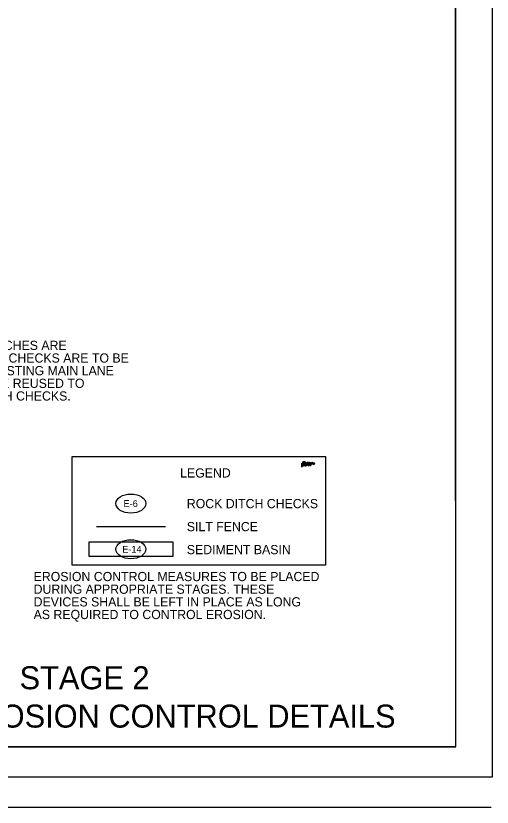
# Model space of a CAD drawing. Extents: x 9844 to 14104, y 9961 to 11067.
# Drawn here: x 11294 to 11605, y 9961 to 10477 of the extents above; entities that cross this region are included whole.
import ezdxf

# ---------------------------------------------------------------- set-up
doc = ezdxf.new("R2010")
doc.units = 0
for name, color, linetype in [('Legend', 7, 'Continuous'), ('R_Border', 7, 'Continuous'), ('R_No Plot', 7, 'Continuous'), ('R_NoPlot', 7, 'Continuous'), ('Stage 2 Ditch Checks', 7, 'Continuous'), ('TEXT', 7, 'Continuous')]:
    doc.layers.add(name, color=color, linetype=linetype)

msp = doc.modelspace()

# ---------------------------------------------------------------- linework, layer by layer
at = {"layer": 'Legend'}
for p, q in [((11480.29, 10183.63), (11481.49, 10184.33)), ((11480.29, 10183.1), (11481.69, 10183.92)), ((11480.29, 10182.58), (11481.9, 10183.5)), ((11481.57, 10185.41), (11482.5, 10185.41)), ((11482.52, 10185.39), (11482.62, 10184.8)), ((11483.84, 10184.29), (11483.84, 10184.3)), ((11483.84, 10183.49), (11483.84, 10183.49)), ((11483.85, 10185.3), (11483.85, 10185.3)), ((11483.85, 10184.49), (11483.85, 10184.49)), ((11483.85, 10183.51), (11483.85, 10183.51)), ((11483.86, 10183.46), (11484.04, 10183.46)), ((11483.87, 10184.51), (11483.87, 10184.51)), ((11483.87, 10184.47), (11484.05, 10184.47)), ((11483.87, 10184.25), (11483.87, 10183.53)), ((11483.88, 10185.26), (11483.88, 10184.54)), ((11484.03, 10183.97), (11484.03, 10184.19)), ((11484.03, 10183.53), (11484.03, 10183.85)), ((11484.04, 10184.92), (11484.04, 10185.21)), ((11484.05, 10184.54), (11484.05, 10184.77)), ((11484.05, 10183.5), (11484.05, 10183.51)), ((11484.06, 10184.8), (11484.31, 10184.87)), ((11484.06, 10184.51), (11484.06, 10184.51)), ((11484.06, 10184.21), (11484.45, 10184.21)), ((11484.34, 10183.95), (11484.06, 10183.95)), ((11484.06, 10183.87), (11484.34, 10183.87)), ((11484.06, 10183.49), (11484.06, 10183.49)), ((11484.07, 10185.24), (11484.15, 10185.24)), ((11484.2, 10184.96), (11484.08, 10184.9)), ((11484.08, 10184.49), (11484.08, 10184.49)), ((11484.37, 10183.84), (11484.37, 10183.83)), ((11484.49, 10184.18), (11484.49, 10184.16)), ((11484.61, 10184.49), (11484.61, 10184.49)), ((11484.62, 10183.47), (11484.83, 10183.47)), ((11484.63, 10184.47), (11484.84, 10184.47)), ((11484.78, 10184.05), (11484.63, 10184.05)), ((11484.63, 10184.01), (11484.63, 10184.01)), ((11484.64, 10185.02), (11484.64, 10185.01)), ((11484.64, 10183.99), (11484.64, 10183.53)), ((11484.79, 10185.06), (11484.65, 10185.06)), ((11484.66, 10184.99), (11484.66, 10184.54)), ((11484.8, 10183.54), (11484.8, 10184.03)), ((11484.82, 10184.54), (11484.82, 10185.04)), ((11484.83, 10183.51), (11484.83, 10183.51)), ((11484.84, 10184.51), (11484.84, 10184.52)), ((11485, 10183.46), (11485.21, 10183.46)), ((11485.16, 10184.05), (11485.01, 10184.05)), ((11485.01, 10184.01), (11485.01, 10184.01)), ((11485.02, 10183.99), (11485.02, 10183.53)), ((11485.18, 10183.53), (11485.18, 10183.86)), ((11485.21, 10183.51), (11485.21, 10183.51)), ((11485.38, 10184.9), (11485.45, 10184.98)), ((11485.53, 10184.47), (11485.73, 10184.47)), ((11485.53, 10184.01), (11485.53, 10184.01)), ((11485.68, 10185.32), (11485.54, 10185.32)), ((11485.54, 10185.28), (11485.54, 10185.28)), ((11485.54, 10183.99), (11485.54, 10183.53)), ((11485.55, 10185.26), (11485.55, 10184.53)), ((11485.71, 10184.86), (11485.71, 10185.3)), ((11485.71, 10184.69), (11485.78, 10184.75)), ((11485.71, 10184.53), (11485.71, 10184.67)), ((11485.71, 10183.54), (11485.71, 10183.86)), ((11485.73, 10183.51), (11485.73, 10183.51)), ((11485.9, 10184.97), (11485.75, 10184.84)), ((11485.82, 10184.74), (11485.94, 10184.53)), ((11485.89, 10185.04), (11485.9, 10185)), ((11486.12, 10185.07), (11485.91, 10185.07)), ((11485.91, 10183.51), (11485.91, 10183.51)), ((11485.93, 10184.47), (11486.19, 10184.47)), ((11485.93, 10183.86), (11485.93, 10183.54)), ((11485.95, 10184.9), (11486.1, 10185.03)), ((11486.15, 10184.52), (11485.95, 10184.87)), ((11486.09, 10183.54), (11486.09, 10183.87)), ((11486.12, 10185.03), (11486.13, 10185.03)), ((11486.12, 10183.51), (11486.12, 10183.51)), ((11486.14, 10185.04), (11486.14, 10185.05)), ((11486.32, 10184.9), (11486.32, 10184.9)), ((11486.32, 10183.87), (11486.32, 10183.53)), ((11486.33, 10184.82), (11486.68, 10184.82)), ((11486.53, 10184.87), (11486.34, 10184.87)), ((11486.48, 10183.54), (11486.48, 10183.87)), ((11486.51, 10183.51), (11486.5, 10183.51)), ((11486.68, 10184.62), (11486.68, 10184.62)), ((11486.78, 10184.47), (11487, 10184.47)), ((11486.79, 10185.02), (11486.79, 10185.01)), ((11486.95, 10185.06), (11486.8, 10185.06)), ((11486.81, 10184.99), (11486.81, 10184.54)), ((11486.97, 10184.54), (11486.97, 10184.87)), ((11487, 10184.51), (11486.99, 10184.52)), ((11487.25, 10184.47), (11487.46, 10184.47)), ((11487.26, 10185.02), (11487.26, 10185.01)), ((11487.42, 10185.06), (11487.27, 10185.06)), ((11487.28, 10184.99), (11487.28, 10184.54)), ((11487.44, 10184.54), (11487.44, 10185.03)), ((11487.46, 10184.51), (11487.46, 10184.52)), ((11487.57, 10184.47), (11487.78, 10184.47)), ((11487.58, 10185.02), (11487.58, 10185.01)), ((11487.73, 10185.06), (11487.59, 10185.06)), ((11487.6, 10184.99), (11487.6, 10184.54)), ((11487.76, 10184.54), (11487.76, 10184.87)), ((11487.78, 10184.51), (11487.78, 10184.52)), ((11487.96, 10184.47), (11488.17, 10184.47)), ((11487.98, 10184.87), (11487.98, 10184.54)), ((11488.14, 10184.54), (11488.14, 10184.87)), ((11488.17, 10184.51), (11488.17, 10184.52)), ((11488.84, 10185.06), (11488.61, 10185.06)), ((11488.67, 10184.94), (11488.67, 10184.65)), ((11488.69, 10184.46), (11488.69, 10184.46)), ((11488.81, 10184.63), (11488.81, 10184.98)), ((11488.82, 10185), (11488.86, 10185.02)), ((11346.58, 10143.59), (11391.58, 10143.59))]:
    msp.add_line(p, q, dxfattribs=at)
msp.add_lwpolyline([(11330.89, 10189.39), (11495.89, 10189.39), (11495.89, 10118.34), (11330.89, 10118.34)], close=True, dxfattribs=at)
for points in [[(11482.95, 10185.07), (11482.83, 10185.76), (11482.81, 10185.78), (11481.24, 10185.78), (11481.22, 10185.76), (11481.09, 10185.05), (11480.25, 10184.57), (11480.24, 10184.54), (11480.24, 10184.17), (11480.28, 10184.15)], [(11481.33, 10184.66), (11480.26, 10184.04), (11480.25, 10184.02), (11480.25, 10183.65), (11480.29, 10183.63)], [(11481.52, 10184.26), (11480.26, 10183.52), (11480.25, 10183.5), (11480.25, 10183.12), (11480.29, 10183.1)], [(11481.72, 10183.86), (11480.26, 10182.99), (11480.25, 10182.97), (11480.25, 10182.6), (11480.29, 10182.58)], [(11480.28, 10184.15), (11481.42, 10184.78), (11481.43, 10184.8), (11481.54, 10185.39)], [(11483.34, 10184.59), (11483.36, 10184.61), (11483.36, 10184.93), (11483.34, 10184.96)], [(11483.34, 10184.14), (11483.36, 10184.17), (11483.36, 10184.49), (11483.34, 10184.51)], [(11483.34, 10183.69), (11483.36, 10183.71), (11483.36, 10184.04), (11483.34, 10184.06)], [(11483.34, 10183.23), (11483.36, 10183.25), (11483.36, 10183.59), (11483.34, 10183.62)], [(11484.49, 10184.32), (11483.86, 10184.32), (11483.86, 10184.32)], [(11484.24, 10185.33), (11483.87, 10185.33), (11483.87, 10185.32)], [(11484.38, 10184.01), (11484.39, 10184.01), (11484.38, 10184.01), (11484.37, 10184), (11484.37, 10183.98)], [(11484.38, 10183.82), (11484.39, 10183.82), (11484.38, 10183.82)], [(11484.39, 10183.83), (11484.4, 10183.83), (11484.4, 10184), (11484.39, 10184)], [(11484.51, 10184.16), (11484.52, 10184.16), (11484.52, 10184.3)], [(11484.6, 10183.49), (11484.6, 10183.49), (11484.6, 10183.49)], [(11484.61, 10184.03), (11484.61, 10184.03), (11484.61, 10184.03)], [(11484.62, 10185.04), (11484.62, 10185.04), (11484.62, 10185.04)], [(11484.62, 10183.51), (11484.62, 10183.51), (11484.62, 10183.51)], [(11484.63, 10184.52), (11484.63, 10184.52), (11484.63, 10184.51)], [(11484.85, 10183.49), (11484.85, 10183.49), (11484.85, 10183.49)], [(11484.86, 10184.49), (11484.86, 10184.49), (11484.86, 10184.49)], [(11484.98, 10183.49), (11484.98, 10183.49), (11484.98, 10183.49)], [(11484.99, 10184.03), (11484.99, 10184.03), (11484.99, 10184.03)], [(11485, 10183.51), (11485, 10183.51), (11485, 10183.51)], [(11485.23, 10183.49), (11485.23, 10183.49), (11485.23, 10183.49)], [(11485.36, 10183.98), (11485.4, 10183.95), (11485.41, 10183.96), (11485.41, 10184.08), (11485.4, 10184.1), (11485.35, 10184.1)], [(11485.39, 10184.48), (11485.43, 10184.47), (11485.44, 10184.48), (11485.44, 10184.61)], [(11485.5, 10183.49), (11485.52, 10183.47), (11485.73, 10183.47), (11485.75, 10183.49)], [(11485.7, 10184.04), (11485.68, 10184.05), (11485.53, 10184.05), (11485.51, 10184.03)], [(11485.52, 10183.51), (11485.52, 10183.51), (11485.52, 10183.51)], [(11485.53, 10184.52), (11485.53, 10184.52), (11485.53, 10184.51)], [(11485.73, 10184.51), (11485.73, 10184.52), (11485.73, 10184.52)], [(11485.89, 10183.49), (11485.91, 10183.47), (11486.12, 10183.47), (11486.14, 10183.49)], [(11485.93, 10184.52), (11485.93, 10184.52), (11485.93, 10184.51)], [(11486.19, 10184.51), (11486.18, 10184.52), (11486.17, 10184.52)], [(11486.27, 10183.49), (11486.29, 10183.47), (11486.51, 10183.47), (11486.53, 10183.49)], [(11486.3, 10183.51), (11486.3, 10183.51), (11486.29, 10183.51)], [(11486.65, 10184.48), (11486.69, 10184.47), (11486.7, 10184.48), (11486.7, 10184.61)], [(11486.76, 10184.49), (11486.76, 10184.49), (11486.76, 10184.49)], [(11486.78, 10185.04), (11486.78, 10185.03), (11486.78, 10185.04)], [(11486.79, 10184.52), (11486.79, 10184.52), (11486.78, 10184.51)], [(11487.02, 10184.49), (11487.02, 10184.49), (11487.02, 10184.49)], [(11487.15, 10184.99), (11487.19, 10184.95), (11487.2, 10184.97), (11487.2, 10185.09), (11487.19, 10185.1), (11487.13, 10185.1)], [(11487.23, 10184.49), (11487.23, 10184.49), (11487.23, 10184.49)], [(11487.25, 10185.04), (11487.25, 10185.03), (11487.25, 10185.04)], [(11487.26, 10184.52), (11487.25, 10184.52), (11487.25, 10184.51)], [(11487.49, 10184.49), (11487.49, 10184.49), (11487.49, 10184.49)], [(11487.55, 10184.49), (11487.55, 10184.49), (11487.55, 10184.49)], [(11487.57, 10185.04), (11487.57, 10185.03), (11487.57, 10185.04)], [(11487.58, 10184.52), (11487.57, 10184.52), (11487.57, 10184.51)], [(11487.8, 10184.49), (11487.8, 10184.49), (11487.8, 10184.49)], [(11487.94, 10184.49), (11487.94, 10184.49), (11487.94, 10184.49)], [(11487.96, 10184.52), (11487.96, 10184.52), (11487.96, 10184.51)], [(11488.19, 10184.49), (11488.19, 10184.49), (11488.19, 10184.49)], [(11488.37, 10184.31), (11488.37, 10184.36), (11488.36, 10184.38), (11488.32, 10184.4), (11488.22, 10184.32)]]:
    msp.add_lwpolyline(points, dxfattribs=at)
for centre, radius, start, end in [((11482.04, 10183.21), 1.62, 63.44, 116.2443), ((11482.04, 10183.21), 1.24, 63.4399, 116.2445), ((11482.04, 10183.21), 1.16, 63.4396, 116.2455), ((11481.57, 10185.39), 0.0257, 90, 169.3947), ((11482.04, 10183.21), 0.79, 63.4406, 116.2427), ((11482.04, 10183.21), 0.717, 63.443, 116.2359), ((11482.04, 10183.21), 0.326, 63.4385, 116.2484), ((11483.36, 10185.86), 2.63, 243.4196, 269.4358), ((11483.36, 10185.86), 2.24, 243.4196, 269.3512), ((11483.36, 10185.86), 2.17, 243.4196, 269.3138), ((11482.5, 10185.39), 0.0257, 9.4561, 90), ((11483.36, 10185.86), 1.79, 243.4196, 269.1919), ((11483.36, 10185.86), 1.72, 243.4196, 269.1297), ((11482.04, 10183.21), 1.69, 63.4196, 69.8726), ((11483.36, 10185.86), 1.34, 243.4196, 268.9264), ((11483.36, 10185.86), 1.27, 243.4196, 268.8202), ((11482.98, 10185.07), 0.0257, 189.9771, 243.8715), ((11483.36, 10185.86), 0.9, 243.8715, 268.4109), ((11483.86, 10184.3), 0.0212, 82.6236, 189.0072), ((11483.86, 10184.3), 0.0212, 181.5218, 256.2604), ((11483.86, 10183.48), 0.021, 103.7396, 178.4782), ((11483.86, 10183.48), 0.021, 170.9928, 274.1452), ((11483.87, 10185.3), 0.0212, 82.6236, 189.0072), ((11483.87, 10185.3), 0.0212, 181.5218, 256.2604), ((11483.87, 10184.49), 0.021, 103.7396, 178.4782), ((11483.87, 10184.49), 0.021, 170.9928, 274.1452), ((11483.84, 10184.25), 0.0259, 358.7571, 66.0872), ((11483.84, 10183.53), 0.0259, 293.9128, 6.4972), ((11483.85, 10185.26), 0.0259, 358.7571, 66.0872), ((11483.85, 10184.54), 0.0259, 293.9128, 6.4972), ((11484.06, 10184.19), 0.0234, 90, 180), ((11484.06, 10183.97), 0.0234, 180, 270), ((11484.06, 10183.85), 0.0234, 90, 180), ((11484.06, 10183.53), 0.0259, 174.5041, 246.0872), ((11484.07, 10185.21), 0.0234, 90, 180), ((11484.07, 10184.92), 0.0234, 180, 295.644), ((11484.04, 10183.48), 0.021, 260.4108, 9.0072), ((11484.07, 10184.77), 0.0234, 115.5876, 180), ((11484.07, 10184.54), 0.0259, 174.5041, 246.0872), ((11484.06, 10184.49), 0.021, 260.4108, 9.0071), ((11484.04, 10183.48), 0.021, 1.5218, 76.2604), ((11484.06, 10184.49), 0.021, 1.5218, 76.2604), ((11484.18, 10185.07), 0.163, 26.6835, 99.2796), ((11483.91, 10185.44), 0.563, 300.9494, 314.2537), ((11484.28, 10184.87), 0.455, 79.5817, 94.0737), ((11484.25, 10185.11), 0.0889, 308.8414, 26.6835), ((11484.06, 10185.45), 0.631, 293.1872, 299.0408), ((11484.34, 10183.98), 0.0351, 270, 0), ((11484.34, 10183.84), 0.0351, 0, 90), ((11484.32, 10185.12), 0.205, 346.8336, 79.1626), ((11484.28, 10185.13), 0.242, 290.3558, 346.8336), ((11484.38, 10183.83), 0.0117, 180, 270), ((11484.38, 10184), 0.0117, 0, 90), ((11484.38, 10183.83), 0.0117, 270, 0), ((11484.45, 10184.18), 0.0351, 360, 90), ((11484.49, 10184.3), 0.0234, 360, 90), ((11484.5, 10184.16), 0.0117, 180, 270), ((11484.5, 10184.16), 0.0117, 270, 0), ((11484.62, 10183.49), 0.0211, 90, 180), ((11484.62, 10183.49), 0.0211, 180, 270), ((11484.63, 10184.49), 0.0211, 90, 179.9884), ((11484.63, 10184.49), 0.0211, 180, 270), ((11484.63, 10184.03), 0.0211, 90, 180), ((11484.63, 10184.03), 0.0211, 180, 250.953), ((11484.65, 10185.04), 0.0211, 90, 180), ((11484.65, 10185.04), 0.0211, 180, 250.953), ((11484.62, 10183.53), 0.0211, 270, 360), ((11484.63, 10184.54), 0.0211, 270, 360), ((11484.62, 10183.99), 0.0234, 0, 70.953), ((11484.63, 10184.99), 0.0234, 0, 70.953), ((11484.74, 10185.23), 0.0853, 0, 180), ((11484.74, 10185.23), 0.0853, 180, 0), ((11484.78, 10184.03), 0.0234, 0, 90), ((11484.79, 10185.04), 0.0234, 0, 90), ((11484.83, 10183.54), 0.0234, 180, 270), ((11484.84, 10184.54), 0.0234, 180, 270), ((11484.83, 10183.49), 0.0211, 360, 90), ((11484.83, 10183.49), 0.0211, 270, 0), ((11484.84, 10184.49), 0.0211, 0, 90), ((11484.84, 10184.49), 0.0211, 270, 0), ((11485.24, 10184.8), 0.335, 159.4493, 258.0401), ((11485.16, 10184.86), 0.236, 89.5501, 165.3049), ((11485, 10183.49), 0.0211, 90, 180), ((11485, 10183.49), 0.0211, 180, 270), ((11485.01, 10184.03), 0.0211, 90, 180), ((11485.01, 10184.03), 0.0211, 180, 250.953), ((11485, 10183.53), 0.0211, 270, 0), ((11485, 10183.99), 0.0234, 360, 70.953), ((11485.41, 10184.8), 0.336, 157.5816, 204.7596), ((11485.24, 10184.84), 0.166, 85.3224, 146.7414), ((11485.3, 10184.8), 0.242, 216.7971, 248.1851), ((11485.15, 10184.62), 0.476, 51.4978, 89.5501), ((11485.16, 10184.03), 0.0234, 31.1414, 90), ((11485.26, 10184.87), 0.404, 257.1029, 287.6234), ((11485.19, 10184.05), 0.0117, 211.1414, 301.6677), ((11485.33, 10183.85), 0.142, 82.1433, 175.2273), ((11485.21, 10183.53), 0.0234, 180, 270), ((11485.43, 10183.66), 0.44, 100.4967, 121.6677), ((11485.28, 10184.79), 0.222, 251.3493, 311.1706), ((11485.21, 10183.49), 0.0211, 360, 90), ((11485.21, 10183.49), 0.0211, 270, 0), ((11485.23, 10184.8), 0.199, 60.5413, 85.3224), ((11485.3, 10184.92), 0.0688, 353.0776, 57.5568), ((11485.34, 10183.97), 0.0234, 33.0334, 82.1433), ((11485.38, 10184.91), 0.0117, 173.0776, 318.3482), ((11485.39, 10184.47), 0.0117, 72.7237, 107.6234), ((11485.43, 10184.61), 0.0117, 0, 131.1706), ((11485.44, 10184.98), 0.0117, 318.3482, 51.4978), ((11485.52, 10183.49), 0.0211, 90, 173.9744), ((11485.53, 10184.49), 0.0211, 90, 180), ((11485.53, 10184.49), 0.0211, 180, 270), ((11485.53, 10184.03), 0.0211, 185.1813, 250.953), ((11485.54, 10185.3), 0.0211, 90, 180), ((11485.54, 10185.3), 0.0211, 180, 250.953), ((11485.52, 10183.53), 0.0211, 270, 0), ((11485.53, 10184.53), 0.0187, 270, 360), ((11485.52, 10183.99), 0.0234, 360, 70.953), ((11485.53, 10185.26), 0.0234, 360, 70.953), ((11485.68, 10185.3), 0.0234, 360, 90), ((11485.71, 10184.05), 0.0117, 211.1414, 301.6677), ((11485.73, 10184.86), 0.0234, 180, 311.0699), ((11485.73, 10184.67), 0.0234, 131.0699, 180), ((11485.73, 10184.53), 0.0187, 180, 270), ((11485.82, 10183.87), 0.114, 354.6239, 185.3761), ((11485.73, 10183.54), 0.0234, 180, 270), ((11485.87, 10183.88), 0.221, 38.0335, 134.0608), ((11485.73, 10184.49), 0.0211, 0, 90), ((11485.73, 10184.49), 0.0211, 270, 0), ((11485.73, 10183.49), 0.0211, 6.0256, 90), ((11485.8, 10184.73), 0.0234, 31.2702, 131.0699), ((11485.91, 10185.05), 0.0234, 90, 199.4367), ((11485.91, 10183.49), 0.0211, 90, 173.9744), ((11485.88, 10184.99), 0.0234, 311.0699, 19.4367), ((11485.93, 10184.49), 0.0211, 90, 180), ((11485.93, 10184.49), 0.0211, 180, 270), ((11485.91, 10183.54), 0.0234, 270, 0), ((11485.93, 10184.53), 0.0117, 270, 31.2702), ((11485.97, 10184.88), 0.0234, 131.0699, 211.2702), ((11486.06, 10184.03), 0.0234, 218.0335, 322.8576), ((11486.26, 10183.88), 0.221, 355.8732, 142.8576), ((11486.21, 10183.88), 0.114, 354.6239, 185.3761), ((11486.12, 10183.54), 0.0234, 180, 270), ((11486.12, 10185.01), 0.0234, 90, 131.0699), ((11486.12, 10185.05), 0.0234, 0, 90), ((11486.12, 10183.49), 0.0211, 6.0256, 90), ((11486.13, 10185.04), 0.0117, 270, 0), ((11486.47, 10184.8), 0.335, 159.4493, 258.0401), ((11486.17, 10184.53), 0.0187, 211.2702, 270), ((11486.39, 10184.86), 0.236, 89.5501, 165.3049), ((11486.19, 10184.49), 0.0211, 0, 90), ((11486.19, 10184.49), 0.0211, 270, 0), ((11486.29, 10183.49), 0.0211, 90, 173.9744), ((11486.33, 10184.79), 0.0234, 90, 181.0387), ((11486.64, 10184.8), 0.336, 181.0387, 204.7596), ((11486.3, 10183.53), 0.0211, 270, 0), ((11486.64, 10184.8), 0.336, 157.5816, 162.6114), ((11486.34, 10184.89), 0.0234, 162.6114, 270), ((11486.44, 10184.89), 0.117, 0.3238, 162.4345), ((11486.53, 10184.8), 0.242, 216.7971, 248.1851), ((11486.38, 10184.62), 0.476, 70.5239, 89.5501), ((11486.5, 10184.99), 0.52, 258.6424, 285.5129), ((11486.52, 10184.85), 0.279, 253.3482, 306.5566), ((11486.5, 10183.54), 0.0234, 180, 270), ((11486.51, 10183.49), 0.0211, 6.0256, 90), ((11486.53, 10184.89), 0.0234, 270, 0.3238), ((11486.48, 10184.85), 0.226, 357.7955, 73.16), ((11486.65, 10184.47), 0.0117, 72.7237, 107.6234), ((11486.68, 10184.84), 0.0234, 270, 11.363), ((11486.69, 10184.61), 0.0117, 360, 131.1706), ((11486.78, 10184.49), 0.0211, 90, 180), ((11486.78, 10184.49), 0.0211, 180, 270), ((11486.8, 10185.04), 0.0211, 90, 180), ((11486.8, 10185.04), 0.0211, 180, 250.953), ((11486.79, 10184.99), 0.0234, 0, 70.953), ((11486.79, 10184.54), 0.0211, 270, 0), ((11486.95, 10185.03), 0.0234, 31.1414, 90), ((11486.98, 10185.05), 0.0117, 211.1414, 301.6677), ((11487.11, 10184.86), 0.142, 82.1433, 175.2273), ((11486.99, 10184.54), 0.0234, 180, 270), ((11487.21, 10184.67), 0.44, 100.4967, 121.6677), ((11487, 10184.49), 0.0211, 0, 90), ((11487, 10184.49), 0.0211, 270, 360), ((11487.13, 10184.97), 0.0234, 33.0334, 82.1433), ((11487.25, 10184.49), 0.0211, 90, 180), ((11487.25, 10184.49), 0.0211, 180, 270), ((11487.27, 10185.04), 0.0211, 90, 180), ((11487.27, 10185.04), 0.0211, 180, 250.953), ((11487.25, 10184.99), 0.0234, 0, 70.953), ((11487.26, 10184.54), 0.0211, 270, 0), ((11487.35, 10185.23), 0.0853, 0, 180), ((11487.35, 10185.23), 0.0853, 180, 0), ((11487.42, 10185.03), 0.0234, 0, 90), ((11487.46, 10184.54), 0.0234, 180, 270), ((11487.46, 10184.49), 0.0211, 0, 90), ((11487.46, 10184.49), 0.0211, 270, 0), ((11487.57, 10184.49), 0.0211, 90, 180), ((11487.57, 10184.49), 0.0211, 180, 270), ((11487.59, 10185.04), 0.0211, 90, 180), ((11487.59, 10185.04), 0.0211, 180, 250.953), ((11487.57, 10184.99), 0.0234, 0, 70.953), ((11487.58, 10184.54), 0.0211, 270, 0), ((11487.73, 10185.03), 0.0234, 31.1414, 90), ((11487.76, 10185.05), 0.0117, 211.1414, 301.6677), ((11487.87, 10184.88), 0.114, 354.6239, 185.3761), ((11487.78, 10184.54), 0.0234, 180, 270), ((11487.92, 10184.88), 0.221, 355.8732, 134.0608), ((11487.78, 10184.49), 0.0211, 0, 90), ((11487.78, 10184.49), 0.0211, 270, 0), ((11487.96, 10184.49), 0.0211, 90, 180), ((11487.96, 10184.49), 0.0211, 180, 270), ((11487.96, 10184.54), 0.0211, 270, 0), ((11488.17, 10184.54), 0.0234, 180, 270), ((11488.17, 10184.49), 0.0211, 0, 90), ((11488.17, 10184.49), 0.0211, 270, 0), ((11488.24, 10184.3), 0.0234, 131.168, 231.4342), ((11488.54, 10184.69), 0.516, 231.4342, 293.5615), ((11488.56, 10184.73), 0.334, 82.2082, 193.6815), ((11488.46, 10184.71), 0.236, 194.6951, 270.4499), ((11488.4, 10184.31), 0.0234, 180, 236.707), ((11488.5, 10184.47), 0.211, 236.707, 290.0983), ((11488.62, 10184.74), 0.225, 83.4753, 215.9717), ((11488.54, 10184.7), 0.138, 223.5865, 338.2119), ((11488.36, 10185.07), 0.606, 280.0346, 297.3499), ((11488.54, 10184.43), 0.158, 282.8124, 14.1312), ((11488.65, 10184.51), 0.0234, 13.323, 128.4784), ((11488.65, 10184.94), 0.0234, 0, 83.4753), ((11489.2, 10184.64), 0.539, 193.323, 199.0669), ((11489.2, 10184.64), 0.539, 199.0669, 199.752), ((11488.64, 10184.39), 0.213, 302.2961, 7.2223), ((11488.83, 10184.98), 0.0234, 135.4319, 180), ((11489.23, 10184.6), 0.419, 175.3173, 204.9345), ((11488.84, 10185.03), 0.0234, 315.4319, 90)]:
    msp.add_arc(centre, radius, start, end, dxfattribs=at)
msp.add_ellipse((11369.08, 10158.59), major_axis=(9.78, 0), ratio=0.638788, dxfattribs=at)
at = {"layer": 'R_Border'}
for p, q in [((11580.9, 10000), (11580.9, 11027.3)), ((11580.9, 10000), (10000, 10000)), ((9843.9, 9960.6), (11603.9, 9960.6))]:
    msp.add_line(p, q, dxfattribs=at)
at = {"layer": 'R_No Plot'}
msp.add_lwpolyline([(10000, 10000), (11580.9, 10000), (11580.3, 10963.3), (11365.4, 10963.3), (11357.31, 10959.87), (11348.49, 10961.4), (11348.26, 10977.9), (11169.6, 10977.9), (11169.6, 11027.3), (10000, 11027.3)], close=True, dxfattribs=at)
msp.add_lwpolyline([(10000, 10000), (11580.9, 10000), (11580.3, 10963.3), (11365.4, 10963.3), (11357.31, 10959.87), (11348.49, 10961.4), (11348.26, 10977.9), (11169.6, 10977.9), (11169.6, 11027.3), (10000, 11027.3)], close=True, dxfattribs=at)
at = {"layer": 'R_NoPlot'}
msp.add_lwpolyline([(9937.96, 11046.77), (11604.66, 11046.77), (11604.66, 9980.09), (9937.96, 9980.09)], close=True, dxfattribs=at)
at = {"layer": 'Stage 2 Ditch Checks'}
for p, q in [((11341.82, 10124.01), (11341.82, 10133.58)), ((11341.82, 10133.58), (11396.34, 10133.58)), ((11396.34, 10133.58), (11396.34, 10124.01)), ((11396.34, 10124.01), (11341.82, 10124.01))]:
    msp.add_line(p, q, dxfattribs=at)
msp.add_ellipse((11369.08, 10128.79), major_axis=(9.7, 0), ratio=0.644392, dxfattribs=at)

# ---------------------------------------------------------------- texts
at = {"layer": 'Legend'}
for s, height, p in [('LEGEND', 6, (11401.21, 10175.59)), ('E-6', 4.464, (11364.3, 10156.36)), ('ROCK DITCH CHECKS', 6, (11405.57, 10155.59)), ('SILT FENCE', 6, (11405.57, 10140.59)), ('SEDIMENT BASIN', 6, (11405.57, 10125.59))]:
    msp.add_text(s, height=height, dxfattribs=at).set_placement(p)
at = {"layer": 'R_Border'}
for s, p in [('STAGE 2', (11296.53, 10037.5)), ('TEMPORARY EROSION CONTROL DETAILS', (11123.73, 10012.5))]:
    msp.add_text(s, height=15, dxfattribs=at).set_placement(p)
at = {"layer": 'Stage 2 Ditch Checks'}
msp.add_text('E-14', height=4.464, rotation=0, dxfattribs=at).set_placement((11363.47, 10126.56))
at = {"layer": 'TEXT'}
for s, p in [('AS THE NEW MAIN LANE DITCHES ARE ', (11175.66, 10258.78)), ('CONSTRUCTED, NEW DITCH CHECKS ARE TO BE ', (11175.66, 10250.53)), ('INSTALLED. ROCK FROM EXISTING MAIN LANE ', (11175.66, 10242.28)), ('DITCHES IN STAGE 1 MAY BE REUSED TO ', (11175.66, 10234.03)), ('CONSTRUCT THE NEW DITCH CHECKS.', (11175.66, 10225.78)), ('EROSION CONTROL MEASURES TO BE PLACED ', (11305.68, 10108.01)), ('DURING APPROPRIATE STAGES. THESE ', (11305.68, 10099.76)), ('DEVICES SHALL BE LEFT IN PLACE AS LONG ', (11305.68, 10091.51)), ('AS REQUIRED TO CONTROL EROSION.', (11305.68, 10083.26))]:
    msp.add_text(s, height=6, dxfattribs=at).set_placement(p)

doc.saveas('drawing.dxf')
